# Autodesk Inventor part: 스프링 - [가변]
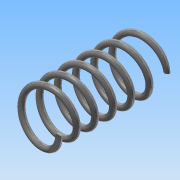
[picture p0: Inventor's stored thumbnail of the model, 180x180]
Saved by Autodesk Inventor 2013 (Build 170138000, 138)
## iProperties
Created: 2017-06
Part Number: 스프링 - [가변]
Material: 강철, 탄소
Document SubType Name: Modeling
Designer: Administrator
Density: 7.87 g/cm^3
Mass: 7.29843 g
Surface Area: 18.9701 cm^2
Volume: 0.927374 cm^3
Author: Administrator
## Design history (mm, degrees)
sketch "스케치1"
  geometry: L1 (0, 0)-(8, 0); L2 (8, 0)-(8, 38); L3 (8, 38)-(0, 38); L4 (0, 38)-(0, 0); C1 r 1 at (8, 0)
  constraints: 8 end point, 2 parallel, 1 centre point, 1 coincident, 1 horizontal, 1 perpendicular
  dimensions: "d0" = 16 diameter of L2 L4; "d2" = 38 distance of L3.end L1.start (derived); "d3" = 2 diameter of C1
feature "코일1" sketch "스케치1" pitch "d4" = 10; turns "d6" = 6; dims "d5" = 38 (= d2), "d7" = 0, angle "d8" = 90 deg, angle "d9" = 90 deg, "d10" = 0, "d11" = 0
sketch "스케치2"
  geometry: L1 (-17.5, 38)-(17.5, 38); L2 (17.5, 38)-(17.5, 0); L3 (17.5, 0)-(-17.5, 0); L4 (-17.5, 0)-(-17.5, 38); 5 further points
  constraints: 8 end point, 2 horizontal alignment, 2 midpoint, 2 parallel, 1 coincident, 1 horizontal, 1 perpendicular
  dimensions: "d12" = 35 distance of L1.start L1.end
extrude "돌출1" sketch "스케치2" stored distance "d14" = 0; taper "d15" = 0 deg
node "솔리드1"
